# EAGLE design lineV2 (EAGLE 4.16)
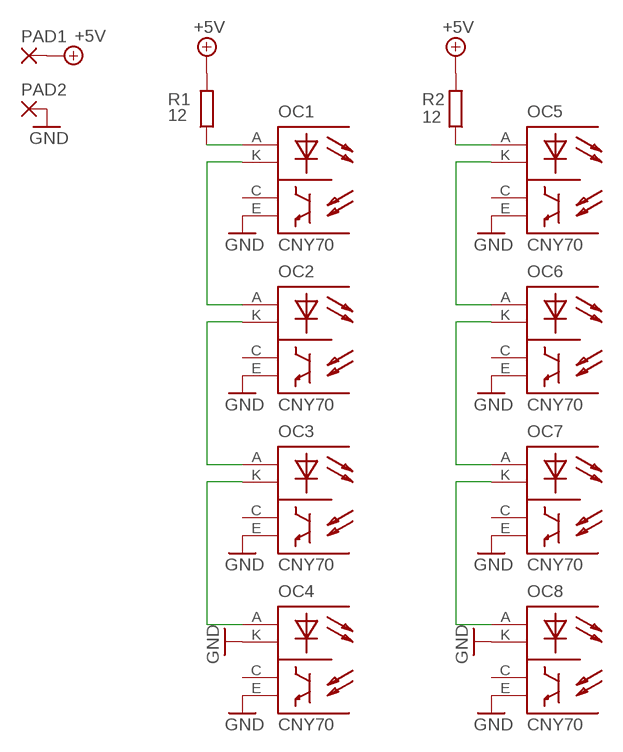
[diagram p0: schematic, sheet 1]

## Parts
OC1  CNY70  [CNY70]
OC2  CNY70  [CNY70]
OC3  CNY70  [CNY70]
OC4  CNY70  [CNY70]
OC5  CNY70  [CNY70]
OC6  CNY70  [CNY70]
OC7  CNY70  [CNY70]
OC8  CNY70  [CNY70]
PAD1  SMD5  [SMD2,54-5,08]
PAD2  SMD5  [SMD2,54-5,08]
R1  12  R-EU_M1206  [M1206]
R2  12  R-EU_M1206  [M1206]

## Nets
+5V: PAD1.1(P) R1.2 R2.2
GND: OC1.E OC2.E OC3.E OC4.E OC4.K OC5.E OC6.E OC7.E OC8.E OC8.K PAD2.1(P)
N$1: OC1.K OC2.A
N$2: OC2.K OC3.A
N$3: OC3.K OC4.A
N$5: OC5.K OC6.A
N$6: OC6.K OC7.A
N$7: OC7.K OC8.A
N$9: OC1.A R1.1
N$10: OC5.A R2.1
Unconnected: OC1.C OC2.C OC3.C OC4.C OC5.C OC6.C OC7.C OC8.C

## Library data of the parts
OC1-OC8 = 0_CNY70:CNY70
PAD1 PAD2 = wirepad:SMD5: SMD PAD
R1 R2 = rcl:R-EU_: RESISTOR, European symbol

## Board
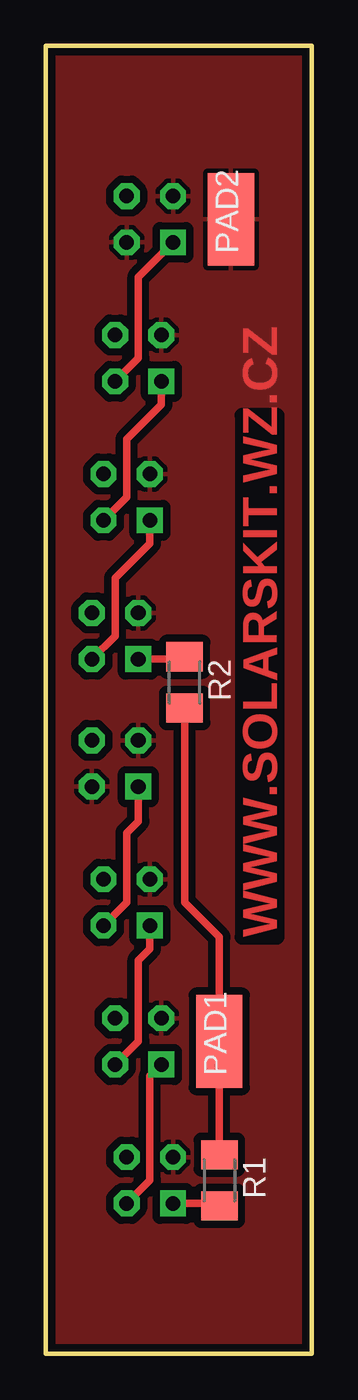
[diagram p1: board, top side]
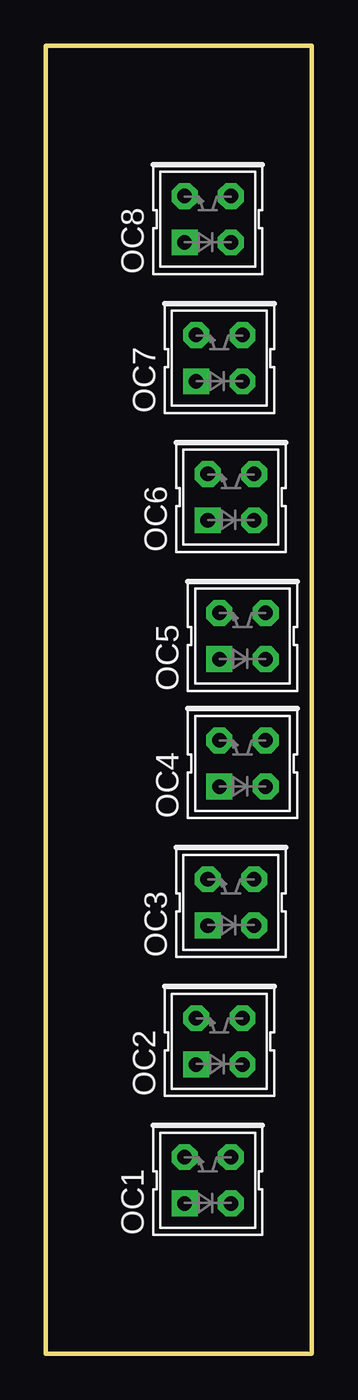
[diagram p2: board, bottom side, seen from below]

Size 14.61 x 71.75 mm. Coordinates in mm from the lower left corner, seen from the top.
Outline: 0,0 14.61,0 14.61,71.75 0,71.75 0,0
Copper layers (1*16): Top 0.035mm / dielectric 1.5mm / Bottom 0.035mm
Design rules "default": minimum track width 10mil, minimum drill 24mil, track to track 8mil, track to pad 8mil, pad to pad 8mil, via to via 8mil, smd to smd 8mil, copper to edge 0.25mm, drill to drill 8mil, minimum pad ring 10mil, minimum via ring 8mil, stop-mask expansion 4mil, vias tented up to drill 0mil, thermal gap 10mil

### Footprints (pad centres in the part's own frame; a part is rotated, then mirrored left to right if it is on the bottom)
CNY70 = drill 0.8 pad 1.422 square: A -1.27,1.27 | drill 0.8 pad 1.422 octagon: C 1.27,-1.27; E 1.27,1.27; K -1.27,-1.27
SMD2,54-5,08 = smd 2.54 x 5.08: 1 0,0
M1206 = smd 1.6 x 2: 1 -1.4,0; 2 1.4,0

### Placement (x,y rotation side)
OC1  5.71,9.52 90 bottom
OC2  5.08,17.14 90 bottom
OC3  4.45,24.77 90 bottom
OC4  3.81,32.38 90 bottom
OC5  3.81,39.37 90 bottom
OC6  4.45,46.99 90 bottom
OC7  5.08,54.61 90 bottom
OC8  5.71,62.23 90 bottom
PAD1  9.53,17.14 0 top
PAD2  10.16,62.23 0 top
R1  9.53,9.52 90 top
R2  7.62,36.83 270 top

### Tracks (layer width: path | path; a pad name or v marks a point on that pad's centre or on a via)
+5V
  Top 0.406: R1.2 PAD1.1 9.53,22.86 7.62,24.77 R2.2 7.62,35.56
GND
  pour Top (isolate 0.406): -0.64,-0.64 15.24,-0.64 15.24,72.39 -0.64,72.39
N$1
  Top 0.406: OC2.A 5.71,15.24 5.71,9.52 OC1.K
N$2
  Top 0.406: OC3.A 5.71,22.23 5.08,21.59 5.08,17.14 OC2.K
N$3
  Top 0.406: OC4.A 5.08,29.21 4.45,28.58 4.45,24.77 OC3.K
N$5
  Top 0.406: OC6.A 5.71,44.45 3.81,42.55 3.81,39.37 OC5.K
N$6
  Top 0.406: OC7.A 6.35,52.07 4.45,50.16 4.45,46.99 OC6.K
N$7
  Top 0.406: OC8.A 5.08,59.05 5.08,54.61 OC7.K
N$9
  Top 0.406: R1.1 9.53,8.25 OC1.A
N$10
  Top 0.406: R2.1 7.62,38.1 OC5.A

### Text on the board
Top: WWW.SOLARSKIT.WZ.CZ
